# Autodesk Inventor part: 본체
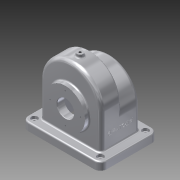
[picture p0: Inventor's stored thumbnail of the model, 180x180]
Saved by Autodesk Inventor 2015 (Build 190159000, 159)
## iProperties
Created: 2017-11
Part Number: 본체
Material: 알루미늄 6061
Document SubType Name: Modeling
Designer: 2-PC07
Density: 2.7 g/cm^3
Appearance: 알루미늄 - 평지
Mass: 1076.56 g
Surface Area: 1180.5 cm^2
Volume: 398.727 cm^3
Author: 2-PC07
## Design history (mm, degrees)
sketch "스케치1"
  geometry: L1 (-58, 0)-(-58, -80); L2 (-58, -80)-(58, -80); L3 (58, -80)-(58, 0); A1 r 58 centre (0, 0) between (58, 0) and (-58, 0); 1 further point
  constraints: 6 end point, 2 point on circle, 2 tangent, 2 vertical, 1 centre point, 1 coincident, 1 perpendicular
  dimensions: "d0" = 116 diameter of A1; "d1" = 80 distance of L2.end L3.end
extrude "돌출1" new body sketch "스케치1" distance "d2" = 38; taper "d3" = 0 deg
sketch "스케치2"
  geometry: L1 (-58, 23)-(-58, 80); L2 (-58, 80)-(58, 80); L3 (58, 80)-(58, 23); L4 (58, 0)-(58, 80) reference; A1 r 58 centre (0, 23) between (-58, 23) and (58, 23); 1 further point
  constraints: 6 end point, 2 point on circle, 1 centre point, 1 perpendicular, 1 point on line, 1 tangent, 1 vertical
  dimensions: "d4" = 116 diameter of A1; "d5" = 57 distance of L1.start L1.end
extrude "돌출2" join sketch "스케치2" distance "d6" = 38; taper "d7" = 0 deg
feature "쉘1" dims "d8" = 5
sketch "스케치3"
  geometry: L1 (-58, -80)-(58, -80) reference; C1 r 37.5 at (0, -15); 1 further point
  constraints: 1 centre point, 1 vertical alignment
  dimensions: "d9" = 75 diameter of C1; "d10" = 65 distance from line of L1 C1.centre
extrude "돌출3" join sketch "스케치3" distance "d11" = 9; taper "d12" = 0 deg
sketch "스케치4"
  geometry: L1 (58, 80)-(-58, 80) reference; C1 r 31 at (0, 15); 1 further point
  constraints: 1 centre point, 1 vertical alignment
  dimensions: "d13" = 62 diameter of C1; "d14" = 65 distance from line of L1 C1.centre
extrude "돌출4" join sketch "스케치4" distance "d15" = 10; taper "d16" = 0 deg
sketch "스케치5"
  geometry: C1 r 16 at (0, 0); C2 r 37.5 at (0, 0) reference; 1 further point
  constraints: 1 centre point, 1 concentric
  dimensions: "d17" = 32 diameter of C1
extrude "돌출5" cut sketch "스케치5" stored distance "d18" = 10; taper "d19" = 0 deg
sketch "스케치6"
  geometry: L1 (-17, -17)-(133, -17); L2 (133, -17)-(133, 93); L3 (133, 93)-(-17, 93); L4 (-17, 93)-(-17, -17); L5 (116, 38)-(0, 38) reference; L6 (116, 0)-(0, 0) reference; L7 (0, 0)-(116, 0); L8 (116, 0)-(116, 76); L9 (116, 76)-(0, 76); L10 (0, 76)-(0, 0); L11 (0, 76)-(116, 76) reference; L12 (116, 0)-(116, 76) reference; 3 further points
  constraints: 16 end point, 4 parallel, 2 collinear, 2 horizontal, 2 midpoint, 2 perpendicular, 1 vertical alignment
  dimensions: "d20" = 110 distance of L1.end L2.end; "d21" = 150 distance of L2.end L3.end; "d22" = 55 distance between parallel lines of L5 L1
extrude "돌출6" join sketch "스케치6" distance "d23" = 15; taper "d24" = 0 deg
fillet "모깎기1" dims "d25" = 12
sketch "스케치7"
  geometry: C1 r 6 at (5, -5); C2 r 6 at (5, 81); C3 r 6 at (-121, 81); C4 r 6 at (-121, -5); A1 r 12 centre (5, 81) between (17, 81) and (5, 93) reference; A2 r 12 centre (-121, 81) between (-121, 93) and (-133, 81) reference; A3 r 12 centre (-121, -5) between (-133, -5) and (-121, -17) reference; A4 r 12 centre (5, -5) between (5, -17) and (17, -5) reference; 1 further point
  constraints: 4 centre point, 4 concentric
  dimensions: "d26" = 12 diameter of C1; "d27" = 12 diameter of C2; "d28" = 12 diameter of C3; "d29" = 12 diameter of C4
extrude "돌출7" cut sketch "스케치7" distance "d30" = 5; taper "d31" = 0 deg
sketch "스케치8"
  geometry: L1 (0, 29)-(0, -29); L2 (-29, 0)-(29, 0); C1 r 37.5 at (0, 0) reference; A1 r 29 centre (0, 0) between (0, 29) and (0, -29); 5 further points
  constraints: 4 coincident, 4 end point, 4 point on circle, 1 centre point, 1 concentric, 1 perpendicular, 1 vertical
  dimensions: "d32" = 58 diameter of A1; "d33" = 58 distance of L1.start L1.end; "d34" = 58 distance of L2.start L2.end
sketch "스케치9"
  geometry: C1 r 2.5 at (0, 0); C2 r 2.5 at (0, 86); C3 r 2.5 at (-126, 86); C4 r 2.5 at (-126, 0); C5 r 6 at (0, 86) reference; C6 r 6 at (0, 0) reference; C7 r 6 at (-126, 86) reference; C8 r 6 at (-126, 0) reference; 1 further point
  constraints: 4 centre point, 4 concentric
  dimensions: "d35" = 5 diameter of C1; "d36" = 5 diameter of C2; "d37" = 5 diameter of C3; "d38" = 5 diameter of C4
extrude "돌출8" cut sketch "스케치9" stored distance "d39" = 5; taper "d40" = 0 deg
fillet "모깎기2" dims "d41" = 8
fillet "모깎기3" dims "d42" = 3
fillet "모깎기4" dims "d43" = 3
fillet "모깎기5" dims "d44" = 3
chamfer "모따기1" distance "d45" = 1; stored, may be unused: second distance "d46" = 2, angle "d47" = 45 deg
node "작업 평면1"
sketch "스케치10"
  geometry: L1 (113, -93)-(13, -93) reference; C1 r 6 at (63, -74); 1 further point
  constraints: 1 centre point, 1 vertical alignment
  dimensions: "d49" = 12 diameter of C1; "d50" = 19 distance from line of C1.centre L1
extrude "돌출9" join sketch "스케치10" stored distance "d51" = 5; taper "d52" = 0 deg
fillet "모깎기6" dims "d53" = 3
sketch "스케치12"
  geometry: L1 (18, 73)-(18, -13) reference; L2 (-62, -8)-(0, -8) reference; 1 further point
  constraints: 1 other
  dimensions: "d54" = 40 distance from line of L1 point (-22, 30); "d55" = 38 distance from line of point (-22, 30) L2
feature "엠보싱1" sketch "스케치12" dims "d0" = 116, "d1" = 80, "d9" = 75, "d10" = 65, "d56" = 0.5, "d57" = 0
sketch "스케치13"
  geometry: L1 (0, -26)-(0, 26); L2 (-26, 0)-(26, 0); C1 r 31 at (0, 0) reference; A1 r 26 centre (0, 0) between (0, -26) and (0, 26); 7 further points
  constraints: 5 coincident, 4 end point, 4 point on circle, 2 midpoint, 1 centre point, 1 concentric, 1 horizontal, 1 vertical
  dimensions: "d58" = 52 diameter of A1; "d59" = 52 distance of L1.start L1.end
hole "구멍1" sketch "스케치8" diameter "d63" = 2.459; stored, may be unused: countersink angle "d67" = 90 deg, drill point angle "d69" = 118 deg; dims "d64" = 6, "d65" = 4, "d66" = 2, "d68" = 8
hole "구멍2" sketch "스케치13" diameter "d70" = 2.459; stored, may be unused: countersink angle "d74" = 90 deg, drill point angle "d76" = 118 deg; dims "d71" = 6, "d72" = 4, "d73" = 2, "d75" = 8
hole "구멍3" diameter "d79" = 4.459; stored, may be unused: countersink angle "d83" = 90 deg, drill point angle "d85" = 118 deg; dims "d80" = 40, "d81" = 4, "d82" = 2, "d84" = 12.8, "d86" = 10, "d87" = 10
node "솔리드1"
other parameters: "d48" = -144
